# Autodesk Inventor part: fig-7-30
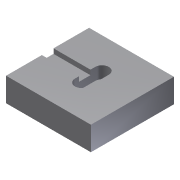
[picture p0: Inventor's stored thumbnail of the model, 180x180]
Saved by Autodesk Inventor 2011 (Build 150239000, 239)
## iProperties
Created: 2004-05
Part Number: fig-7-30
Document SubType Name: Modeling
Designer: CADCIM Technologies
Manufacturer: Standard
Standards Organization: Custom
Density: 1 g/cm^3
Author: CADCIM Technologies
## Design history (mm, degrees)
sketch "Sketch1"
  geometry: L1 (-30.233, -25.517)-(22.302, -25.517); L2 (22.302, -25.517)-(22.302, 25.904); L3 (22.302, 25.904)-(-30.233, 25.904); L4 (-30.233, 25.904)-(-30.233, -25.517)
  constraints: 8 end point, 2 parallel, 1 horizontal, 1 perpendicular
extrude "Extrusion1" new body sketch "Sketch1" distance "d0" = 14.75; taper "d1" = 0 deg
sketch "Sketch2"
  geometry: L1 (1.047, -5.75)-(1.047, 6.846); L2 (-7.35, 6.845)-(-7.35, -5.75); A1 r 4.198 centre (-3.152, 6.846) between (1.047, 6.846) and (-7.35, 6.845); A2 r 4.198 centre (-3.152, -5.75) between (-7.35, -5.75) and (1.047, -5.75)
  constraints: 4 end point, 4 point on circle, 4 tangent, 2 centre point, 1 parallel
extrude "Extrusion2" cut sketch "Sketch2" distance "d2" = 7.5; taper "d3" = 0 deg
sketch "Sketch3"
  geometry: L1 (-7.5, 0)-(-7.5, 12.595) reference; L2 (-7.5, 0)-(0, 0) reference; L3 (-7.5, 2.416)-(-4.537, 2.416); L4 (-4.537, 2.416)-(-4.537, 9.616); L5 (-4.537, 9.616)-(-7.5, 9.616)
  constraints: 6 end point, 2 perpendicular, 2 point on line, 1 parallel
extrude "Extrusion3" cut sketch "Sketch3" stored distance "d4" = 6.75; taper "d5" = 0 deg
body "Solid1"
